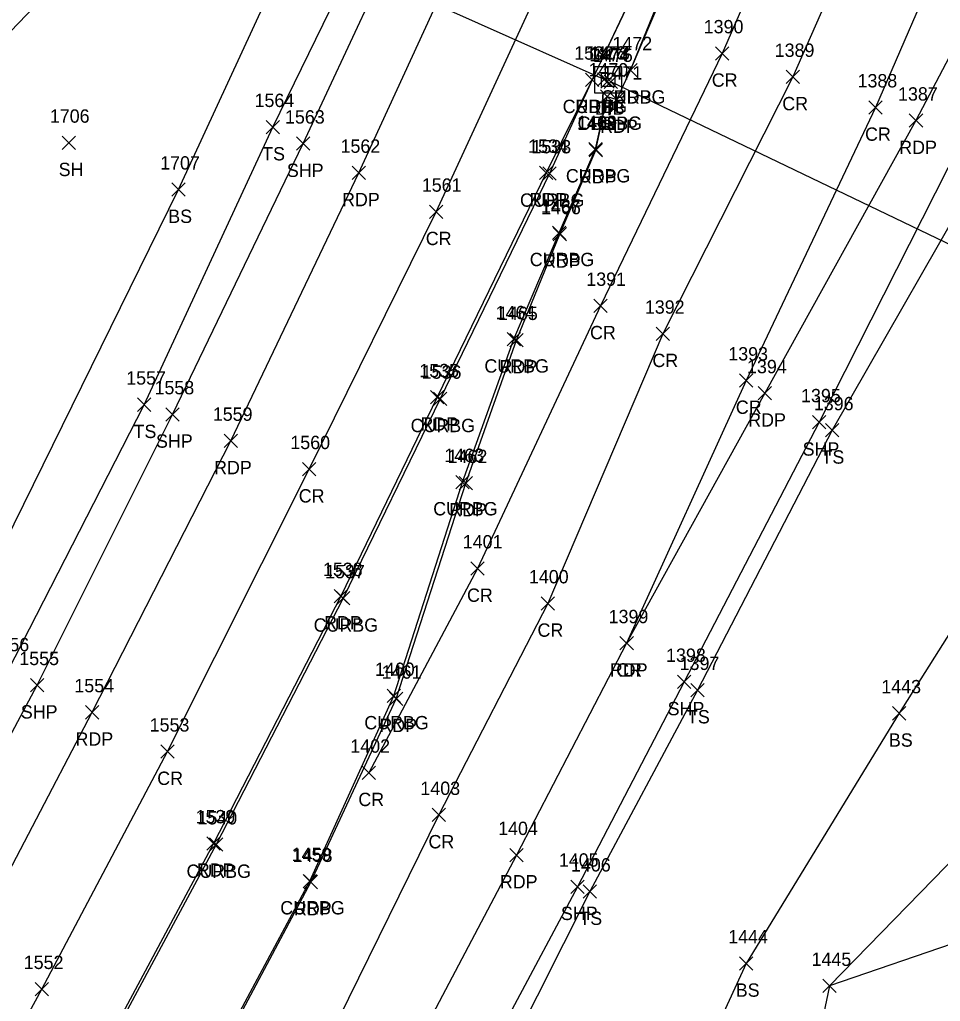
# Model space of a CAD drawing. Extents: x 1623612 to 1625808, y 621345 to 627748.
# Drawn here: x 1624455.5 to 1624593.5, y 625747.8 to 625894.9 of the extents above; entities that cross this region are included whole.
import ezdxf

# ---------------------------------------------------------------- set-up
doc = ezdxf.new("R2010")
doc.units = 0
for name, color, linetype in [('D_A', 7, 'Continuous'), ('D_I', 7, 'Continuous'), ('D_TIC', 7, 'Continuous'), ('DCP', 7, 'Continuous'), ('DS', 7, 'Continuous'), ('L_A', 7, 'Continuous'), ('L_I', 7, 'Continuous'), ('L_TIC', 7, 'Continuous'), ('LAWA', 7, 'Continuous'), ('LELB', 7, 'Continuous'), ('LWET', 7, 'Continuous'), ('P_A', 7, 'Continuous'), ('P_I', 7, 'Continuous'), ('P_TIC', 7, 'Continuous'), ('PET', 7, 'Continuous'), ('PRC', 7, 'Continuous'), ('PSP', 7, 'Continuous'), ('R_A', 7, 'Continuous'), ('R_I', 7, 'Continuous'), ('R_TIC', 7, 'Continuous'), ('RC', 7, 'Continuous')]:
    doc.layers.add(name, color=color, linetype=linetype)

msp = doc.modelspace()

# ---------------------------------------------------------------- linework, layer by layer
at = {"layer": 'D_TIC'}
for points in [[(1624542.09, 625884.86), (1624544.09, 625886.86)], [(1624544.09, 625884.86), (1624542.09, 625886.86)], [(1624542.56, 625884.61), (1624544.56, 625886.61)], [(1624544.56, 625884.61), (1624542.56, 625886.61)], [(1624543.09, 625884.52), (1624545.09, 625886.52)], [(1624545.09, 625884.52), (1624543.09, 625886.52)]]:
    msp.add_lwpolyline(points, dxfattribs=at)
at = {"layer": 'DCP'}
for points in [[(1624543.09, 625885.86), (1624486.55, 625911.08)], [(1624625.52, 625846.45), (1624544.09, 625885.52)]]:
    msp.add_lwpolyline(points, dxfattribs=at)
at = {"layer": 'DS'}
for p, q in [((1624541.65, 625887.85), (1624545.65, 625887.85)), ((1624541.65, 625883.85), (1624541.65, 625887.85)), ((1624545.65, 625887.85), (1624545.65, 625883.85)), ((1624542.65, 625884.85), (1624542.65, 625886.85)), ((1624542.65, 625886.85), (1624544.65, 625886.85)), ((1624544.65, 625886.85), (1624544.65, 625884.85)), ((1624544.65, 625884.85), (1624542.65, 625884.85)), ((1624543.66, 625885.85), (1624543.66, 625885.85)), ((1624543.66, 625885.85), (1624543.66, 625885.85)), ((1624545.65, 625883.85), (1624541.65, 625883.85))]:
    msp.add_line(p, q, dxfattribs=at)
at = {"layer": 'L_TIC'}
for points in [[(1624492.41, 625877.76), (1624494.41, 625879.76)], [(1624494.41, 625877.76), (1624492.41, 625879.76)], [(1624461.83, 625875.41), (1624463.83, 625877.41)], [(1624463.83, 625875.41), (1624461.83, 625877.41)], [(1624478.3, 625868.39), (1624480.3, 625870.39)], [(1624480.3, 625868.39), (1624478.3, 625870.39)], [(1624473.13, 625836.17), (1624475.13, 625838.17)], [(1624475.13, 625836.17), (1624473.13, 625838.17)], [(1624576.24, 625832.33), (1624578.24, 625834.33)], [(1624578.24, 625832.33), (1624576.24, 625834.33)], [(1624556.07, 625793.42), (1624558.07, 625795.42)], [(1624558.07, 625793.42), (1624556.07, 625795.42)], [(1624586.3, 625789.93), (1624588.3, 625791.93)], [(1624588.3, 625789.93), (1624586.3, 625791.93)], [(1624539.93, 625763.23), (1624541.93, 625765.23)], [(1624541.93, 625763.23), (1624539.93, 625765.23)], [(1624563.35, 625752.47), (1624565.35, 625754.47)], [(1624565.35, 625752.47), (1624563.35, 625754.47)], [(1624575.85, 625749.09), (1624577.85, 625751.09)], [(1624577.85, 625749.09), (1624575.85, 625751.09)], [(1624575.85, 625749.09), (1624577.85, 625751.09)], [(1624577.85, 625749.09), (1624575.85, 625751.09)]]:
    msp.add_lwpolyline(points, dxfattribs=at)
at = {"layer": 'LAWA'}
msp.add_lwpolyline([(1624637.25, 625770.76), (1624576.85, 625750.09), (1624565.22, 625694.56), (1624521.74, 625653.69)], dxfattribs=at)
at = {"layer": 'LELB'}
for points in [[(1624405.5, 625728.14), (1624428.24, 625773.19), (1624451.7, 625813.41), (1624479.3, 625869.39), (1624496.23, 625906.08), (1624514.91, 625948.11), (1624536.21, 625990.48), (1624546.45, 626029.66), (1624561.04, 626063.21), (1624576.65, 626110.9), (1624590.48, 626147.32), (1624609.26, 626181.73), (1624628.06, 626219.01), (1624648.51, 626267.43), (1624661.85, 626303.08), (1624661.36, 626343.87), (1624651.86, 626347.04), (1624650.32, 626353.64), (1624652.97, 626362.16), (1624638.4, 626383.22), (1624618.17, 626397.94), (1624604.09, 626415.44)], [(1624414.82, 625722.7), (1624435.62, 625760.87), (1624453.7, 625797.23), (1624474.13, 625837.17), (1624493.41, 625878.76), (1624511.69, 625916.21), (1624528.38, 625951.55), (1624544.66, 625990.22), (1624558.02, 626027.25), (1624569.94, 626061.58), (1624576.34, 626070.61), (1624593.27, 626109.93), (1624608.95, 626149.66), (1624624.61, 626188.43), (1624639.61, 626224.64), (1624652.78, 626258.96), (1624662.63, 626284.81), (1624668.95, 626309.14), (1624669.8, 626328.28), (1624669.98, 626343.79)], [(1624955.96, 625983.78), (1624951.7, 625981.09), (1624926.74, 626006.44), (1624903, 626034.62), (1624876.22, 626070.88), (1624844.75, 626108.46), (1624819.16, 626140.11), (1624799.87, 626157.38), (1624783.22, 626162.54), (1624755.55, 626163.6), (1624745.94, 626159.17), (1624742.5, 626157.44), (1624728.24, 626136.03), (1624714.3, 626113.6), (1624699.16, 626074.97), (1624693.78, 626039.85), (1624688.78, 626004.07), (1624672.44, 625966.06), (1624654.5, 625913.12), (1624647.49, 625863.39), (1624632.05, 625839.96), (1624633.8, 625804.37), (1624607.9, 625781.97), (1624576.85, 625750.09)], [(1624703.97, 626118.88), (1624686.38, 626080.62), (1624681.08, 626059.17), (1624675.33, 626051.53), (1624659.81, 626015.24), (1624646.71, 625979.83), (1624626.49, 625919.66), (1624601.19, 625875.12), (1624577.24, 625833.33), (1624557.07, 625794.42), (1624540.93, 625764.23), (1624521.23, 625725.16), (1624501.1, 625688.94), (1624492.6, 625674.09)], [(1624623.85, 625843.99), (1624616.38, 625836.88), (1624604.12, 625817.6), (1624587.3, 625790.93), (1624564.35, 625753.47), (1624542.54, 625705.94), (1624515.98, 625657.65)]]:
    msp.add_lwpolyline(points, dxfattribs=at)
at = {"layer": 'LWET'}
msp.add_lwpolyline([(1624362.47, 625753.11), (1624386.95, 625796), (1624412.3, 625837.76), (1624446.85, 625885.6), (1624474.51, 625914.41), (1624486.36, 625910.16), (1624487.21, 625914.04), (1624468.66, 625928.53), (1624478.34, 625960.64)], dxfattribs=at)
at = {"layer": 'P_TIC'}
for points in [[(1624559.77, 625888.8), (1624561.77, 625890.8)], [(1624561.77, 625888.8), (1624559.77, 625890.8)], [(1624546, 625886.27), (1624548, 625888.27)], [(1624548, 625886.27), (1624546, 625888.27)], [(1624540.27, 625884.85), (1624542.27, 625886.85)], [(1624542.27, 625884.85), (1624540.27, 625886.85)], [(1624570.33, 625885.27), (1624572.33, 625887.27)], [(1624572.33, 625885.27), (1624570.33, 625887.27)], [(1624542.5, 625882.34), (1624544.5, 625884.34)], [(1624544.5, 625882.34), (1624542.5, 625884.34)], [(1624543.97, 625881.88), (1624545.97, 625883.88)], [(1624545.97, 625881.88), (1624543.97, 625883.88)], [(1624582.74, 625880.7), (1624584.74, 625882.7)], [(1624584.74, 625880.7), (1624582.74, 625882.7)], [(1624588.8, 625878.72), (1624590.8, 625880.72)], [(1624590.8, 625878.72), (1624588.8, 625880.72)], [(1624496.98, 625875.28), (1624498.98, 625877.28)], [(1624498.98, 625875.28), (1624496.98, 625877.28)], [(1624540.8, 625874.32), (1624542.8, 625876.32)], [(1624542.8, 625874.32), (1624540.8, 625876.32)], [(1624505.3, 625870.9), (1624507.3, 625872.9)], [(1624507.3, 625870.9), (1624505.3, 625872.9)], [(1624533.37, 625870.9), (1624535.37, 625872.9)], [(1624535.37, 625870.9), (1624533.37, 625872.9)], [(1624516.91, 625865.07), (1624518.91, 625867.07)], [(1624518.91, 625865.07), (1624516.91, 625867.07)], [(1624535.42, 625861.69), (1624537.42, 625863.69)], [(1624537.42, 625861.69), (1624535.42, 625863.69)], [(1624541.51, 625850.97), (1624543.51, 625852.97)], [(1624543.51, 625850.97), (1624541.51, 625852.97)], [(1624550.87, 625846.8), (1624552.87, 625848.8)], [(1624552.87, 625846.8), (1624550.87, 625848.8)], [(1624528.91, 625845.85), (1624530.91, 625847.85)], [(1624530.91, 625845.85), (1624528.91, 625847.85)], [(1624563.37, 625839.79), (1624565.37, 625841.79)], [(1624565.37, 625839.79), (1624563.37, 625841.79)], [(1624517.06, 625837.28), (1624519.06, 625839.28)], [(1624519.06, 625837.28), (1624517.06, 625839.28)], [(1624566.17, 625837.88), (1624568.17, 625839.88)], [(1624568.17, 625837.88), (1624566.17, 625839.88)], [(1624477.38, 625834.72), (1624479.38, 625836.72)], [(1624479.38, 625834.72), (1624477.38, 625836.72)], [(1624574.28, 625833.53), (1624576.28, 625835.53)], [(1624576.28, 625833.53), (1624574.28, 625835.53)], [(1624486.12, 625830.75), (1624488.12, 625832.75)], [(1624488.12, 625830.75), (1624486.12, 625832.75)], [(1624497.86, 625826.51), (1624499.86, 625828.51)], [(1624499.86, 625826.51), (1624497.86, 625828.51)], [(1624521.35, 625824.42), (1624523.35, 625826.42)], [(1624523.35, 625824.42), (1624521.35, 625826.42)], [(1624523.08, 625811.63), (1624525.08, 625813.63)], [(1624525.08, 625811.63), (1624523.08, 625813.63)], [(1624502.61, 625807.5), (1624504.61, 625809.5)], [(1624504.61, 625807.5), (1624502.61, 625809.5)], [(1624533.65, 625806.4), (1624535.65, 625808.4)], [(1624535.65, 625806.4), (1624533.65, 625808.4)], [(1624545.44, 625800.43), (1624547.44, 625802.43)], [(1624547.44, 625800.43), (1624545.44, 625802.43)], [(1624545.44, 625800.43), (1624547.44, 625802.43)], [(1624547.44, 625800.43), (1624545.44, 625802.43)], [(1624554.05, 625794.64), (1624556.05, 625796.64)], [(1624556.05, 625794.64), (1624554.05, 625796.64)], [(1624457.11, 625794.15), (1624459.11, 625796.15)], [(1624459.11, 625794.15), (1624457.11, 625796.15)], [(1624510.9, 625792.12), (1624512.9, 625794.12)], [(1624512.9, 625792.12), (1624510.9, 625794.12)], [(1624465.36, 625790.08), (1624467.36, 625792.08)], [(1624467.36, 625790.08), (1624465.36, 625792.08)], [(1624476.65, 625784.2), (1624478.65, 625786.2)], [(1624478.65, 625784.2), (1624476.65, 625786.2)], [(1624506.8, 625781.03), (1624508.8, 625783.03)], [(1624508.8, 625781.03), (1624506.8, 625783.03)], [(1624517.3, 625774.7), (1624519.3, 625776.7)], [(1624519.3, 625774.7), (1624517.3, 625776.7)], [(1624483.54, 625770.45), (1624485.54, 625772.45)], [(1624485.54, 625770.45), (1624483.54, 625772.45)], [(1624528.95, 625768.7), (1624530.95, 625770.7)], [(1624530.95, 625768.7), (1624528.95, 625770.7)], [(1624498.1, 625764.66), (1624500.1, 625766.66)], [(1624500.1, 625764.66), (1624498.1, 625766.66)], [(1624538.05, 625763.96), (1624540.05, 625765.96)], [(1624540.05, 625763.96), (1624538.05, 625765.96)], [(1624457.78, 625748.62), (1624459.78, 625750.62)], [(1624459.78, 625748.62), (1624457.78, 625750.62)]]:
    msp.add_lwpolyline(points, dxfattribs=at)
at = {"layer": 'PET'}
for points in [[(1624425.67, 625715.65), (1624447.22, 625754.54), (1624466.36, 625791.08), (1624487.12, 625831.75), (1624506.3, 625871.9), (1624524.08, 625910.61), (1624540.03, 625946.09), (1624556.56, 625984.64), (1624572.71, 626022.65), (1624589.71, 626064.03), (1624605.99, 626104.3), (1624622.34, 626144.13), (1624637.91, 626182.32), (1624652.97, 626219.87), (1624666.22, 626252.76), (1624676.12, 626279.69), (1624681.8, 626301.06), (1624682.54, 626327.48), (1624678.38, 626346.43)], [(1624700.76, 626272.27), (1624689.28, 626244.04), (1624672.95, 626203.67), (1624657.22, 626165.07), (1624639.97, 626122.42), (1624626.87, 626089.89), (1624609.23, 626047.25), (1624593.09, 626008.04), (1624578.04, 625971.53), (1624565.57, 625940.71), (1624555.47, 625915.78), (1624541.27, 625885.85), (1624534.37, 625871.9), (1624518.06, 625838.28), (1624503.61, 625808.5), (1624484.54, 625771.45), (1624465.59, 625736.05), (1624447.42, 625703.06)], [(1624697.29, 626122.48), (1624678.78, 626081.29), (1624660.95, 626038.77), (1624644.98, 625998.6), (1624626.67, 625954.13), (1624613.79, 625925.45), (1624589.8, 625879.72), (1624567.17, 625838.88), (1624546.44, 625801.43), (1624529.95, 625769.7), (1624509.63, 625731.24), (1624490.24, 625695.36), (1624481.98, 625680.63)], [(1624460.07, 625693.53), (1624483.15, 625735.74), (1624499.1, 625765.66), (1624511.9, 625793.12), (1624522.35, 625825.42), (1624529.91, 625846.85), (1624536.42, 625862.69), (1624541.8, 625875.32), (1624543.5, 625883.34), (1624544.97, 625882.88), (1624547, 625887.27), (1624554.88, 625905.73), (1624572.42, 625947.53), (1624589.16, 625987.94), (1624606.66, 626030.36), (1624622.98, 626070.33), (1624637.54, 626106.17)]]:
    msp.add_lwpolyline(points, dxfattribs=at)
at = {"layer": 'PRC'}
for points in [[(1624436.82, 625709.28), (1624458.78, 625749.62), (1624477.65, 625785.2), (1624498.86, 625827.51), (1624517.91, 625866.07), (1624535.88, 625905.07), (1624552.01, 625941.13), (1624568.1, 625980.06), (1624584.2, 626018.31), (1624601.56, 626060.15), (1624617.86, 626100.59), (1624633.9, 626140.47), (1624649.73, 626177.64), (1624664.57, 626215.84), (1624677.89, 626248.35), (1624689.08, 626275.05), (1624700.91, 626304.1), (1624709.94, 626325.53), (1624717.47, 626344.65), (1624728.1, 626371.26)], [(1624746.78, 626345.22), (1624728.92, 626300.56), (1624706.67, 626243.05), (1624691.9, 626206.9), (1624679.69, 626176.67), (1624663.83, 626137.95), (1624646.8, 626096.72), (1624629.43, 626053.71), (1624612.52, 626011.13), (1624595.71, 625970.86), (1624582, 625938.5), (1624560.77, 625889.8), (1624542.51, 625851.97), (1624524.08, 625812.63), (1624507.8, 625782.03)], [(1624756.75, 626332.96), (1624737.87, 626288.85), (1624717.83, 626237.45), (1624702.63, 626201.76), (1624690.94, 626172.24), (1624674.42, 626133.37), (1624657.37, 626090.13), (1624639.98, 626048.33), (1624623.77, 626007.33), (1624605.45, 625965.01), (1624592.56, 625934.47), (1624571.33, 625886.27), (1624551.87, 625847.8), (1624534.65, 625807.4), (1624518.3, 625775.7), (1624498.78, 625736.03), (1624480.71, 625702.14), (1624471.41, 625686.57)], [(1624760.82, 626312.53), (1624746.49, 626278.01), (1624728.27, 626233.28), (1624713.29, 626195.84), (1624701.88, 626168.74), (1624685.25, 626128.21), (1624667.86, 626085.49), (1624650.83, 626043.68), (1624633.95, 626002.72), (1624616.32, 625959.56), (1624604.63, 625929.9), (1624583.74, 625881.7), (1624564.37, 625840.79), (1624546.44, 625801.43)]]:
    msp.add_lwpolyline(points, dxfattribs=at)
at = {"layer": 'PSP'}
for points in [[(1624417.68, 625720.8), (1624438.84, 625759.11), (1624458.11, 625795.15), (1624478.38, 625835.72), (1624497.98, 625876.28), (1624515.71, 625914.28), (1624531.6, 625950.04), (1624547.22, 625988.82), (1624563.29, 626026.94), (1624580.72, 626068.16), (1624597.18, 626108), (1624613.35, 626148.06), (1624629.33, 626186.41), (1624644.21, 626222.86), (1624657.67, 626256.77), (1624667.93, 626283.18), (1624675.15, 626305.88), (1624676.55, 626327.48), (1624673.72, 626344.86)], [(1624701.4, 626121.26), (1624681.91, 626079.85), (1624663.33, 626037.3), (1624647.64, 625997), (1624629.31, 625952.35), (1624617.52, 625923.63), (1624596.53, 625876.44), (1624575.28, 625834.53), (1624555.05, 625795.64), (1624539.05, 625764.96), (1624518.58, 625726.57), (1624499, 625690.51), (1624490.77, 625675.48)]]:
    msp.add_lwpolyline(points, dxfattribs=at)
at = {"layer": 'R_TIC'}
for points in [[(1624546, 625886.27), (1624548, 625888.27)], [(1624548, 625886.27), (1624546, 625888.27)], [(1624540.27, 625884.85), (1624542.27, 625886.85)], [(1624542.27, 625884.85), (1624540.27, 625886.85)], [(1624542.5, 625882.34), (1624544.5, 625884.34)], [(1624544.5, 625882.34), (1624542.5, 625884.34)], [(1624540.75, 625874.46), (1624542.75, 625876.46)], [(1624542.75, 625874.46), (1624540.75, 625876.46)], [(1624533.86, 625870.82), (1624535.86, 625872.82)], [(1624535.86, 625870.82), (1624533.86, 625872.82)], [(1624535.34, 625861.92), (1624537.34, 625863.92)], [(1624537.34, 625861.92), (1624535.34, 625863.92)], [(1624528.54, 625845.97), (1624530.54, 625847.97)], [(1624530.54, 625845.97), (1624528.54, 625847.97)], [(1624517.48, 625837.05), (1624519.48, 625839.05)], [(1624519.48, 625837.05), (1624517.48, 625839.05)], [(1624520.86, 625824.58), (1624522.86, 625826.58)], [(1624522.86, 625824.58), (1624520.86, 625826.58)], [(1624502.94, 625807.16), (1624504.94, 625809.16)], [(1624504.94, 625807.16), (1624502.94, 625809.16)], [(1624510.54, 625792.53), (1624512.54, 625794.53)], [(1624512.54, 625792.53), (1624510.54, 625794.53)], [(1624483.9, 625770.28), (1624485.9, 625772.28)], [(1624485.9, 625770.28), (1624483.9, 625772.28)], [(1624497.94, 625764.8), (1624499.94, 625766.8)], [(1624499.94, 625764.8), (1624497.94, 625766.8)]]:
    msp.add_lwpolyline(points, dxfattribs=at)
at = {"layer": 'RC'}
for points in [[(1624700.99, 626272.06), (1624689.6, 626244.03), (1624673.22, 626203.62), (1624657.61, 626165.02), (1624640.13, 626122.2), (1624627.02, 626089.91), (1624609.59, 626047.26), (1624593.5, 626007.85), (1624578.4, 625971.27), (1624565.79, 625940.64), (1624555.58, 625915.85), (1624541.27, 625885.85), (1624534.86, 625871.82), (1624518.48, 625838.05), (1624503.94, 625808.16), (1624484.9, 625771.28), (1624465.88, 625735.89), (1624447.8, 625702.94)], [(1624547, 625887.27), (1624554.6, 625905.92), (1624572.12, 625947.84), (1624588.93, 625987.87), (1624606.24, 626030.63), (1624622.62, 626070.4), (1624637.36, 626106.36), (1624639.98, 626113.52)], [(1624459.81, 625693.66), (1624482.94, 625735.87), (1624498.94, 625765.8), (1624511.54, 625793.53), (1624521.86, 625825.58), (1624529.54, 625846.97), (1624536.34, 625862.92), (1624541.75, 625875.46), (1624543.5, 625883.34)]]:
    msp.add_lwpolyline(points, dxfattribs=at)

# ---------------------------------------------------------------- texts
at = {"layer": 'D_A'}
for s, p in [('DIB', (1624541.66, 625880.61)), ('P', (1624542.47, 625880.86)), ('DI', (1624542.71, 625880.85)), ('P', (1624543.47, 625880.52))]:
    msp.add_text(s, height=2, dxfattribs=at).set_placement(p)
at = {"layer": 'D_I'}
for s, p in [('1476', (1624540.34, 625888.86)), ('1473', (1624540.96, 625888.85)), ('1474', (1624540.86, 625888.61)), ('1475', (1624541.4, 625888.52))]:
    msp.add_text(s, height=2, dxfattribs=at).set_placement(p)
at = {"layer": 'L_A'}
for s, p in [('TS', (1624491.82, 625873.76)), ('SH', (1624461.32, 625871.41)), ('BS', (1624477.74, 625864.39)), ('TS', (1624472.54, 625832.17)), ('TS', (1624575.64, 625828.33)), ('TS', (1624555.48, 625789.42)), ('BS', (1624585.74, 625785.93)), ('TS', (1624539.34, 625759.23)), ('BS', (1624562.79, 625748.47))]:
    msp.add_text(s, height=2, dxfattribs=at).set_placement(p)
at = {"layer": 'L_I'}
for s, p in [('1564', (1624490.67, 625881.76)), ('1706', (1624460, 625879.41)), ('1707', (1624476.53, 625872.39)), ('1557', (1624471.44, 625840.17)), ('1396', (1624574.49, 625836.33)), ('1556', (1624450.95, 625800.23)), ('1397', (1624554.38, 625797.42)), ('1443', (1624584.61, 625793.93)), ('1406', (1624538.1, 625767.23)), ('1444', (1624561.66, 625756.47)), ('1445', (1624574.15, 625753.09)), ('1445', (1624574.15, 625753.09))]:
    msp.add_text(s, height=2, dxfattribs=at).set_placement(p)
at = {"layer": 'P_A'}
for s, p in [('CR', (1624559.2, 625884.8)), ('RDP', (1624544.49, 625882.27)), ('RDP', (1624538.75, 625880.85)), ('CR', (1624569.76, 625881.27)), ('RDP', (1624540.99, 625878.34)), ('RDP', (1624542.46, 625877.88)), ('CR', (1624582.17, 625876.7)), ('RDP', (1624587.29, 625874.72)), ('SHP', (1624495.52, 625871.28)), ('RDP', (1624539.29, 625870.32)), ('RDP', (1624503.79, 625866.9)), ('RDP', (1624531.86, 625866.9)), ('CR', (1624516.34, 625861.07)), ('RDP', (1624533.91, 625857.69)), ('CR', (1624540.95, 625846.97)), ('RDP', (1624527.4, 625841.85)), ('CR', (1624550.3, 625842.8)), ('CR', (1624562.8, 625835.79)), ('RDP', (1624515.54, 625833.28)), ('RDP', (1624564.66, 625833.88)), ('SHP', (1624475.91, 625830.72)), ('SHP', (1624572.81, 625829.53)), ('RDP', (1624484.61, 625826.75)), ('CR', (1624497.3, 625822.51)), ('RDP', (1624519.84, 625820.42)), ('CR', (1624522.52, 625807.63)), ('RDP', (1624501.1, 625803.5)), ('CR', (1624533.08, 625802.4)), ('RDP', (1624543.93, 625796.43)), ('CR', (1624544.87, 625796.43)), ('SHP', (1624455.65, 625790.15)), ('SHP', (1624552.58, 625790.64)), ('RDP', (1624509.39, 625788.12)), ('RDP', (1624463.85, 625786.08)), ('CR', (1624476.09, 625780.2)), ('CR', (1624506.23, 625777.03)), ('CR', (1624516.74, 625770.7)), ('RDP', (1624482.03, 625766.45)), ('RDP', (1624527.44, 625764.7)), ('RDP', (1624496.58, 625760.66)), ('SHP', (1624536.59, 625759.96))]:
    msp.add_text(s, height=2, dxfattribs=at).set_placement(p)
at = {"layer": 'P_I'}
for s, p in [('1390', (1624557.99, 625892.8)), ('1472', (1624544.31, 625890.27)), ('1532', (1624538.57, 625888.85)), ('1389', (1624568.63, 625889.27)), ('1470', (1624540.72, 625886.34)), ('1471', (1624542.84, 625885.88)), ('1388', (1624581.04, 625884.7)), ('1387', (1624587.11, 625882.72)), ('1563', (1624495.24, 625879.28)), ('1469', (1624539.05, 625878.32)), ('1562', (1624503.56, 625874.9)), ('1534', (1624531.67, 625874.9)), ('1561', (1624515.74, 625869.07)), ('1466', (1624533.62, 625865.69)), ('1391', (1624540.39, 625854.97)), ('1392', (1624549.17, 625850.8)), ('1465', (1624527.17, 625849.85)), ('1393', (1624561.67, 625843.79)), ('1394', (1624564.48, 625841.88)), ('1535', (1624515.36, 625841.28)), ('1558', (1624475.68, 625838.72)), ('1395', (1624572.58, 625837.53)), ('1559', (1624484.42, 625834.75)), ('1560', (1624496.04, 625830.51)), ('1462', (1624519.61, 625828.42)), ('1401', (1624521.88, 625815.63)), ('1538', (1624500.92, 625811.5)), ('1400', (1624531.79, 625810.4)), ('1399', (1624543.74, 625804.43)), ('1399', (1624543.74, 625804.43)), ('1555', (1624455.42, 625798.15)), ('1398', (1624552.35, 625798.64)), ('1461', (1624509.73, 625796.12)), ('1554', (1624463.67, 625794.08)), ('1553', (1624474.96, 625788.2)), ('1402', (1624505.03, 625785.03)), ('1403', (1624515.53, 625778.7)), ('1539', (1624481.84, 625774.45)), ('1404', (1624527.18, 625772.7)), ('1458', (1624496.4, 625768.66)), ('1405', (1624536.28, 625767.96)), ('1552', (1624456.09, 625752.62))]:
    msp.add_text(s, height=2, dxfattribs=at).set_placement(p)
at = {"layer": 'R_A'}
for p in [(1624542.59, 625882.27), (1624536.85, 625880.85), (1624539.08, 625878.34), (1624537.33, 625870.46), (1624530.45, 625866.82), (1624531.92, 625857.92), (1624525.12, 625841.97), (1624514.06, 625833.05), (1624517.45, 625820.58), (1624499.53, 625803.16), (1624507.12, 625788.53), (1624480.48, 625766.28), (1624494.53, 625760.8)]:
    msp.add_text('CURBG', height=2, dxfattribs=at).set_placement(p)
at = {"layer": 'R_I'}
for s, p in [('1472', (1624544.31, 625890.27)), ('1532', (1624538.57, 625888.85)), ('1470', (1624540.72, 625886.34)), ('1468', (1624539.01, 625878.46)), ('1533', (1624532.17, 625874.82)), ('1467', (1624533.59, 625865.92)), ('1464', (1624526.8, 625849.97)), ('1536', (1624515.73, 625841.05)), ('1463', (1624519.12, 625828.58)), ('1537', (1624501.25, 625811.16)), ('1460', (1624508.71, 625796.53)), ('1540', (1624482.12, 625774.28)), ('1459', (1624496.24, 625768.8))]:
    msp.add_text(s, height=2, dxfattribs=at).set_placement(p)

doc.saveas('drawing.dxf')
